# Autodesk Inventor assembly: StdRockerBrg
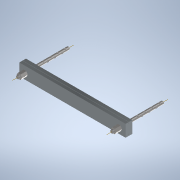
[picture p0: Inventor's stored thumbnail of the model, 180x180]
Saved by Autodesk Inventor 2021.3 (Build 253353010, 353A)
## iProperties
RuleStatus: InUse
Created: 2019-05
Part Number: StdRockerBrg
Document SubType Name: Assembly
Designer: u1426
AnchorBoltEmbed: 15.000 in
MasonryPLThickness: 1.500 in
SolePLThickness: 1.250 in
BearingLength: 44.000 in
NoSwedges: 4.000 in
ExpansionCapLength: 24.000 in
AnchorDiameter: 1.250 in
AnchorEdgeDist: 2.500 in
BearingWidth: 5.000 in
Author: u1426
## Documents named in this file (5)
- S:\Bridge_CADD\Other\SampleBridgeInventor\StdRockerBrgEXP.iam
- S:\Bridge_CADD\Other\SampleBridgeInventor\StdRockerBrgMasonry.ipt
- S:\Bridge_CADD\Other\SampleBridgeInventor\StdRockerBrgSole.ipt
- S:\Bridge_CADD\Other\SampleBridgeInventor\AnchorBolt.ipt
- S:\Bridge_CADD\Other\SampleBridgeInventor\ANSI B18.2.2 - 1 1_4 - 7(8).ipt
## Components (8 placed, 4 different names)
1. StdRockerBrgMasonry:1 — Flush:3, Flush:4, Mate:4, Mate:5, Flush:29, Mate:29, Mate:30, Flush:12, Mate to UCSXY, Mate to USCXZ, Mate to USCYZ
2. StdRockerBrgSole:1 — Mate:1, Flush:11, Flush:29
3. AnchorBolt:1 — Flush:3, Mate:4, Mate:17, Mate:29
4. AnchorBolt:2 — Flush:4, Mate:5, Mate:19, Mate:30
5. Heavy Hex Nut - Inch 1 1/4 - 7:1 — Mate:17
6. Heavy Hex Nut - Inch 1 1/4 - 7:2
7. Heavy Hex Nut - Inch 1 1/4 - 7:3 — Mate:19
8. Heavy Hex Nut - Inch 1 1/4 - 7:4
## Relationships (15: Mate 10, Flush 5)
- Mate:1: StdRockerBrgSole:1
- Flush:3: StdRockerBrgMasonry:1 ↔ AnchorBolt:1
- Flush:4: StdRockerBrgMasonry:1 ↔ AnchorBolt:2
- Mate:4: StdRockerBrgMasonry:1 ↔ AnchorBolt:1
- Mate:5: StdRockerBrgMasonry:1 ↔ AnchorBolt:2
- Mate:17: AnchorBolt:1 ↔ Heavy Hex Nut - Inch 1 1/4 - 7:1
- Mate:19: AnchorBolt:2 ↔ Heavy Hex Nut - Inch 1 1/4 - 7:3
- Flush:11: StdRockerBrgSole:1
- Flush:29: StdRockerBrgMasonry:1 ↔ StdRockerBrgSole:1
- Mate:29: StdRockerBrgMasonry:1 ↔ AnchorBolt:1
- Mate:30: StdRockerBrgMasonry:1 ↔ AnchorBolt:2
- Flush:12: StdRockerBrgMasonry:1
- Mate to UCSXY: StdRockerBrgMasonry:1
- Mate to USCXZ: StdRockerBrgMasonry:1
- Mate to USCYZ: StdRockerBrgMasonry:1
## Named parameters: EmbedConcrete = 381 mm, Protrusion = 152.4 mm
